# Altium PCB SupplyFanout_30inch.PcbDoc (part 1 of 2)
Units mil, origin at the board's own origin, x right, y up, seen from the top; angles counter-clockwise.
Board outline 6605 x 4500 mil, 4 copper layers (Top Layer, Int1 (GND), Int2 (PWR), Bottom Layer), stack 53.912 mil thick; 152 components, 62 nets, 512 pads, 47 vias.
Unrouted connection lines stored in the file: 85.
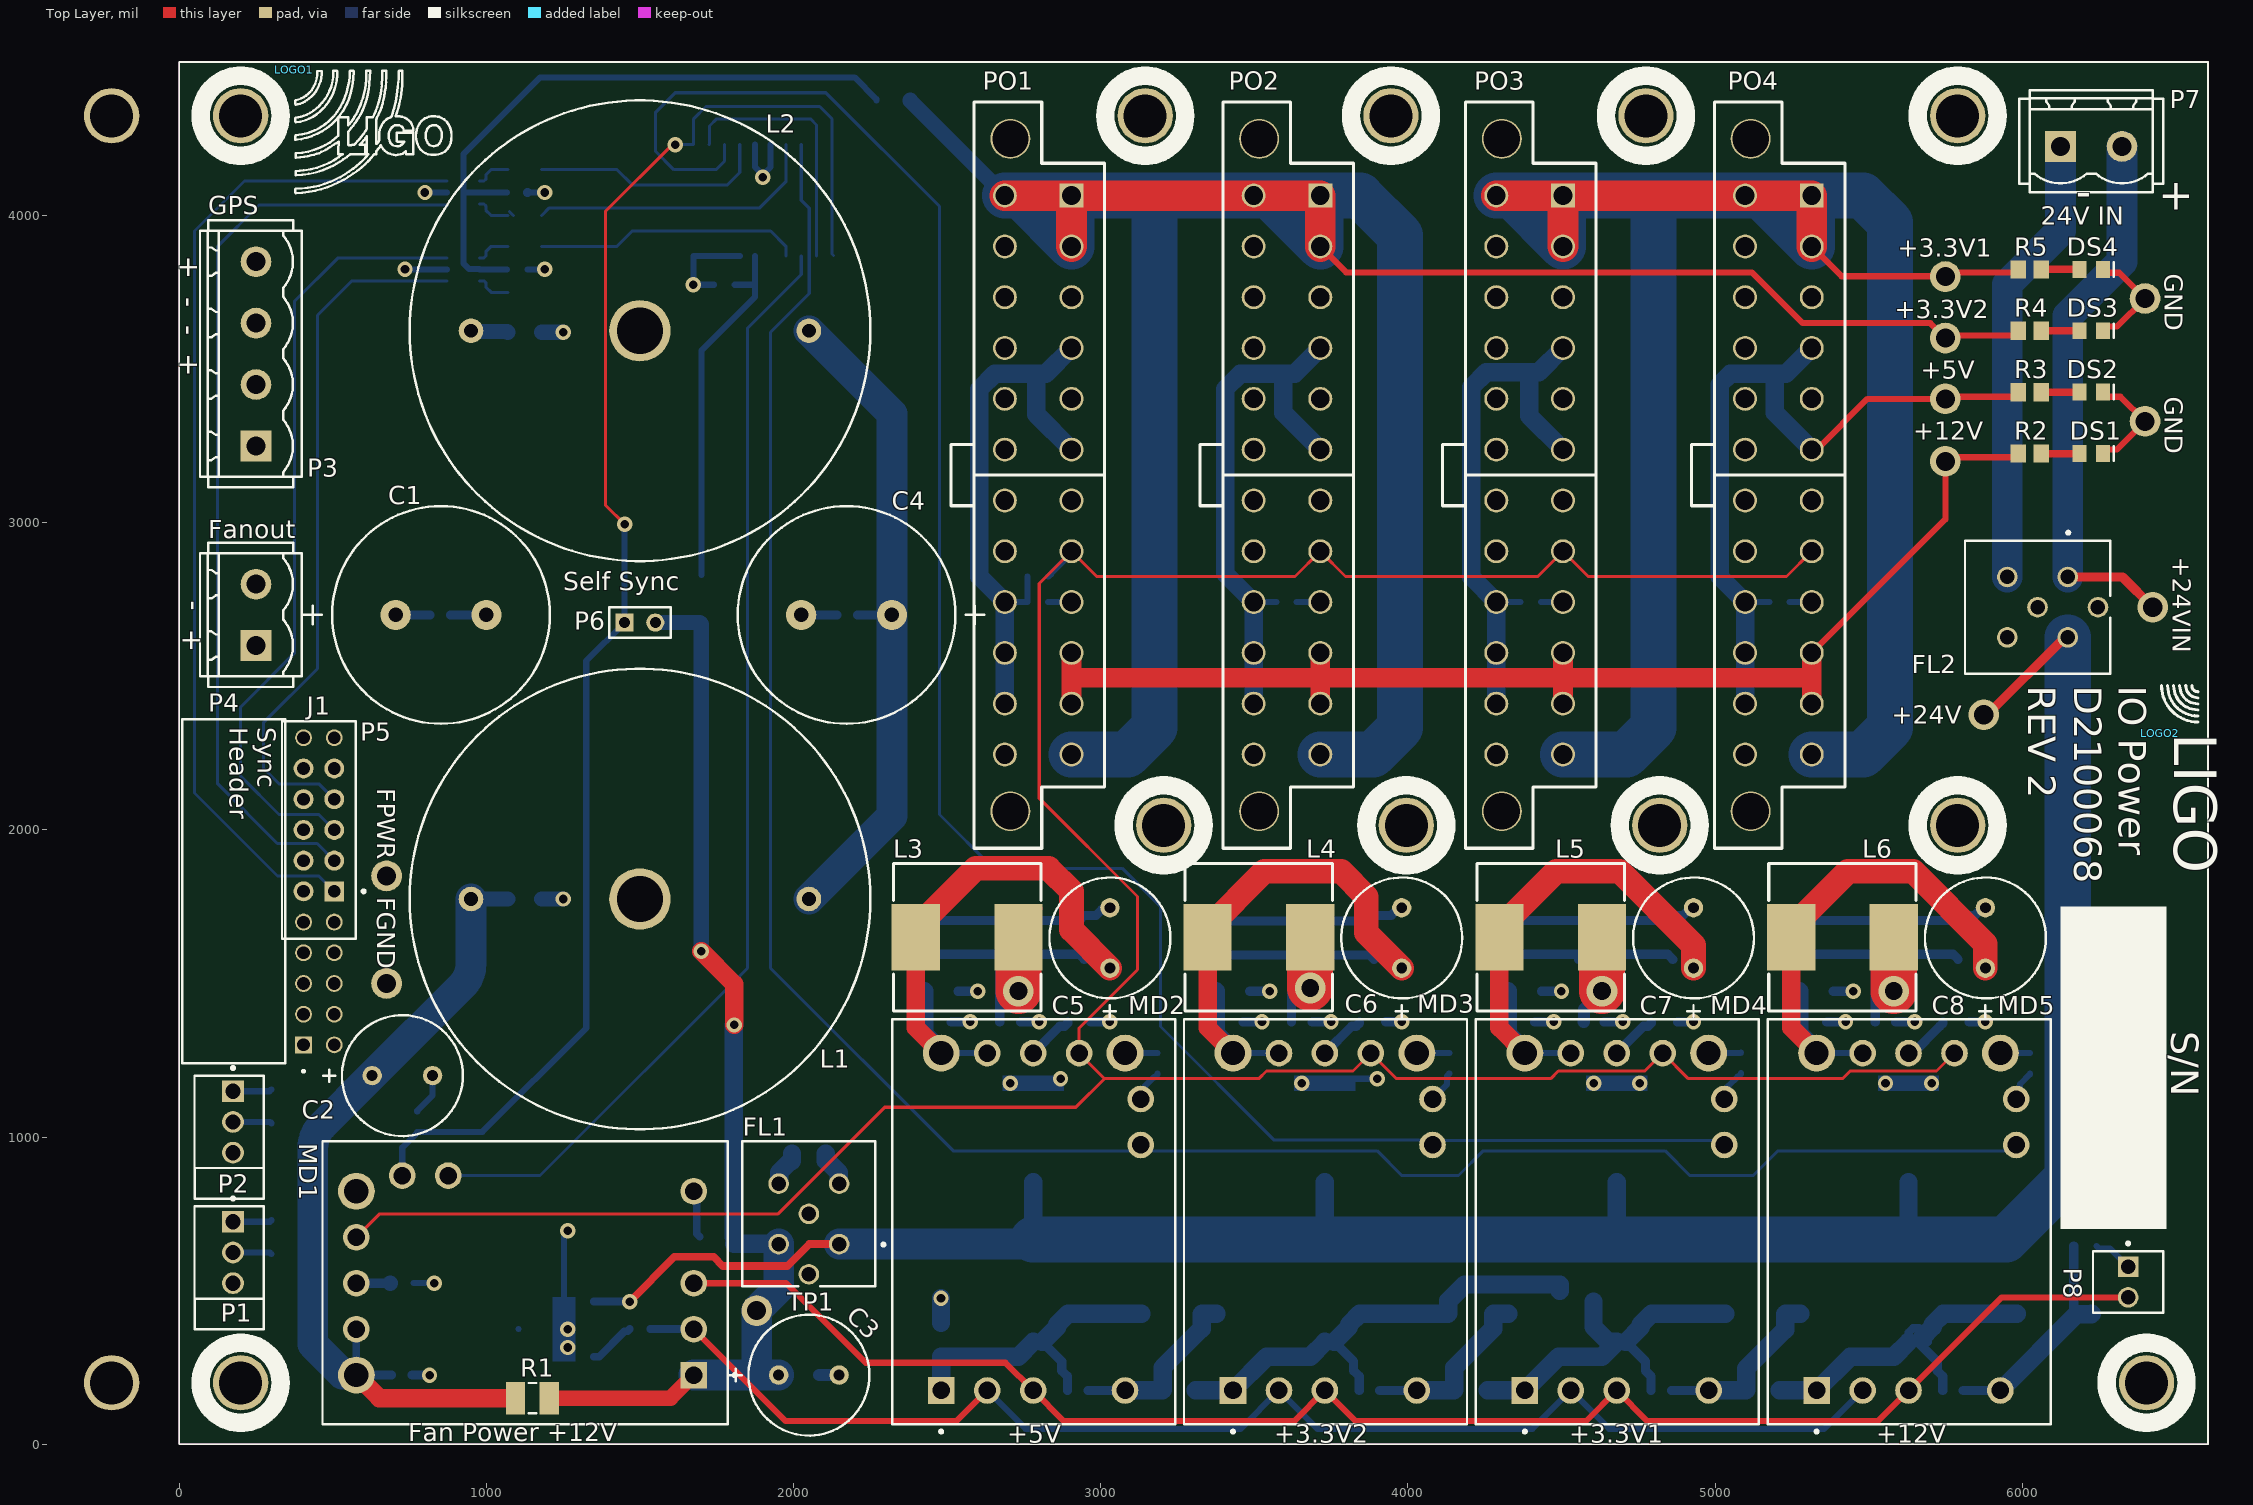
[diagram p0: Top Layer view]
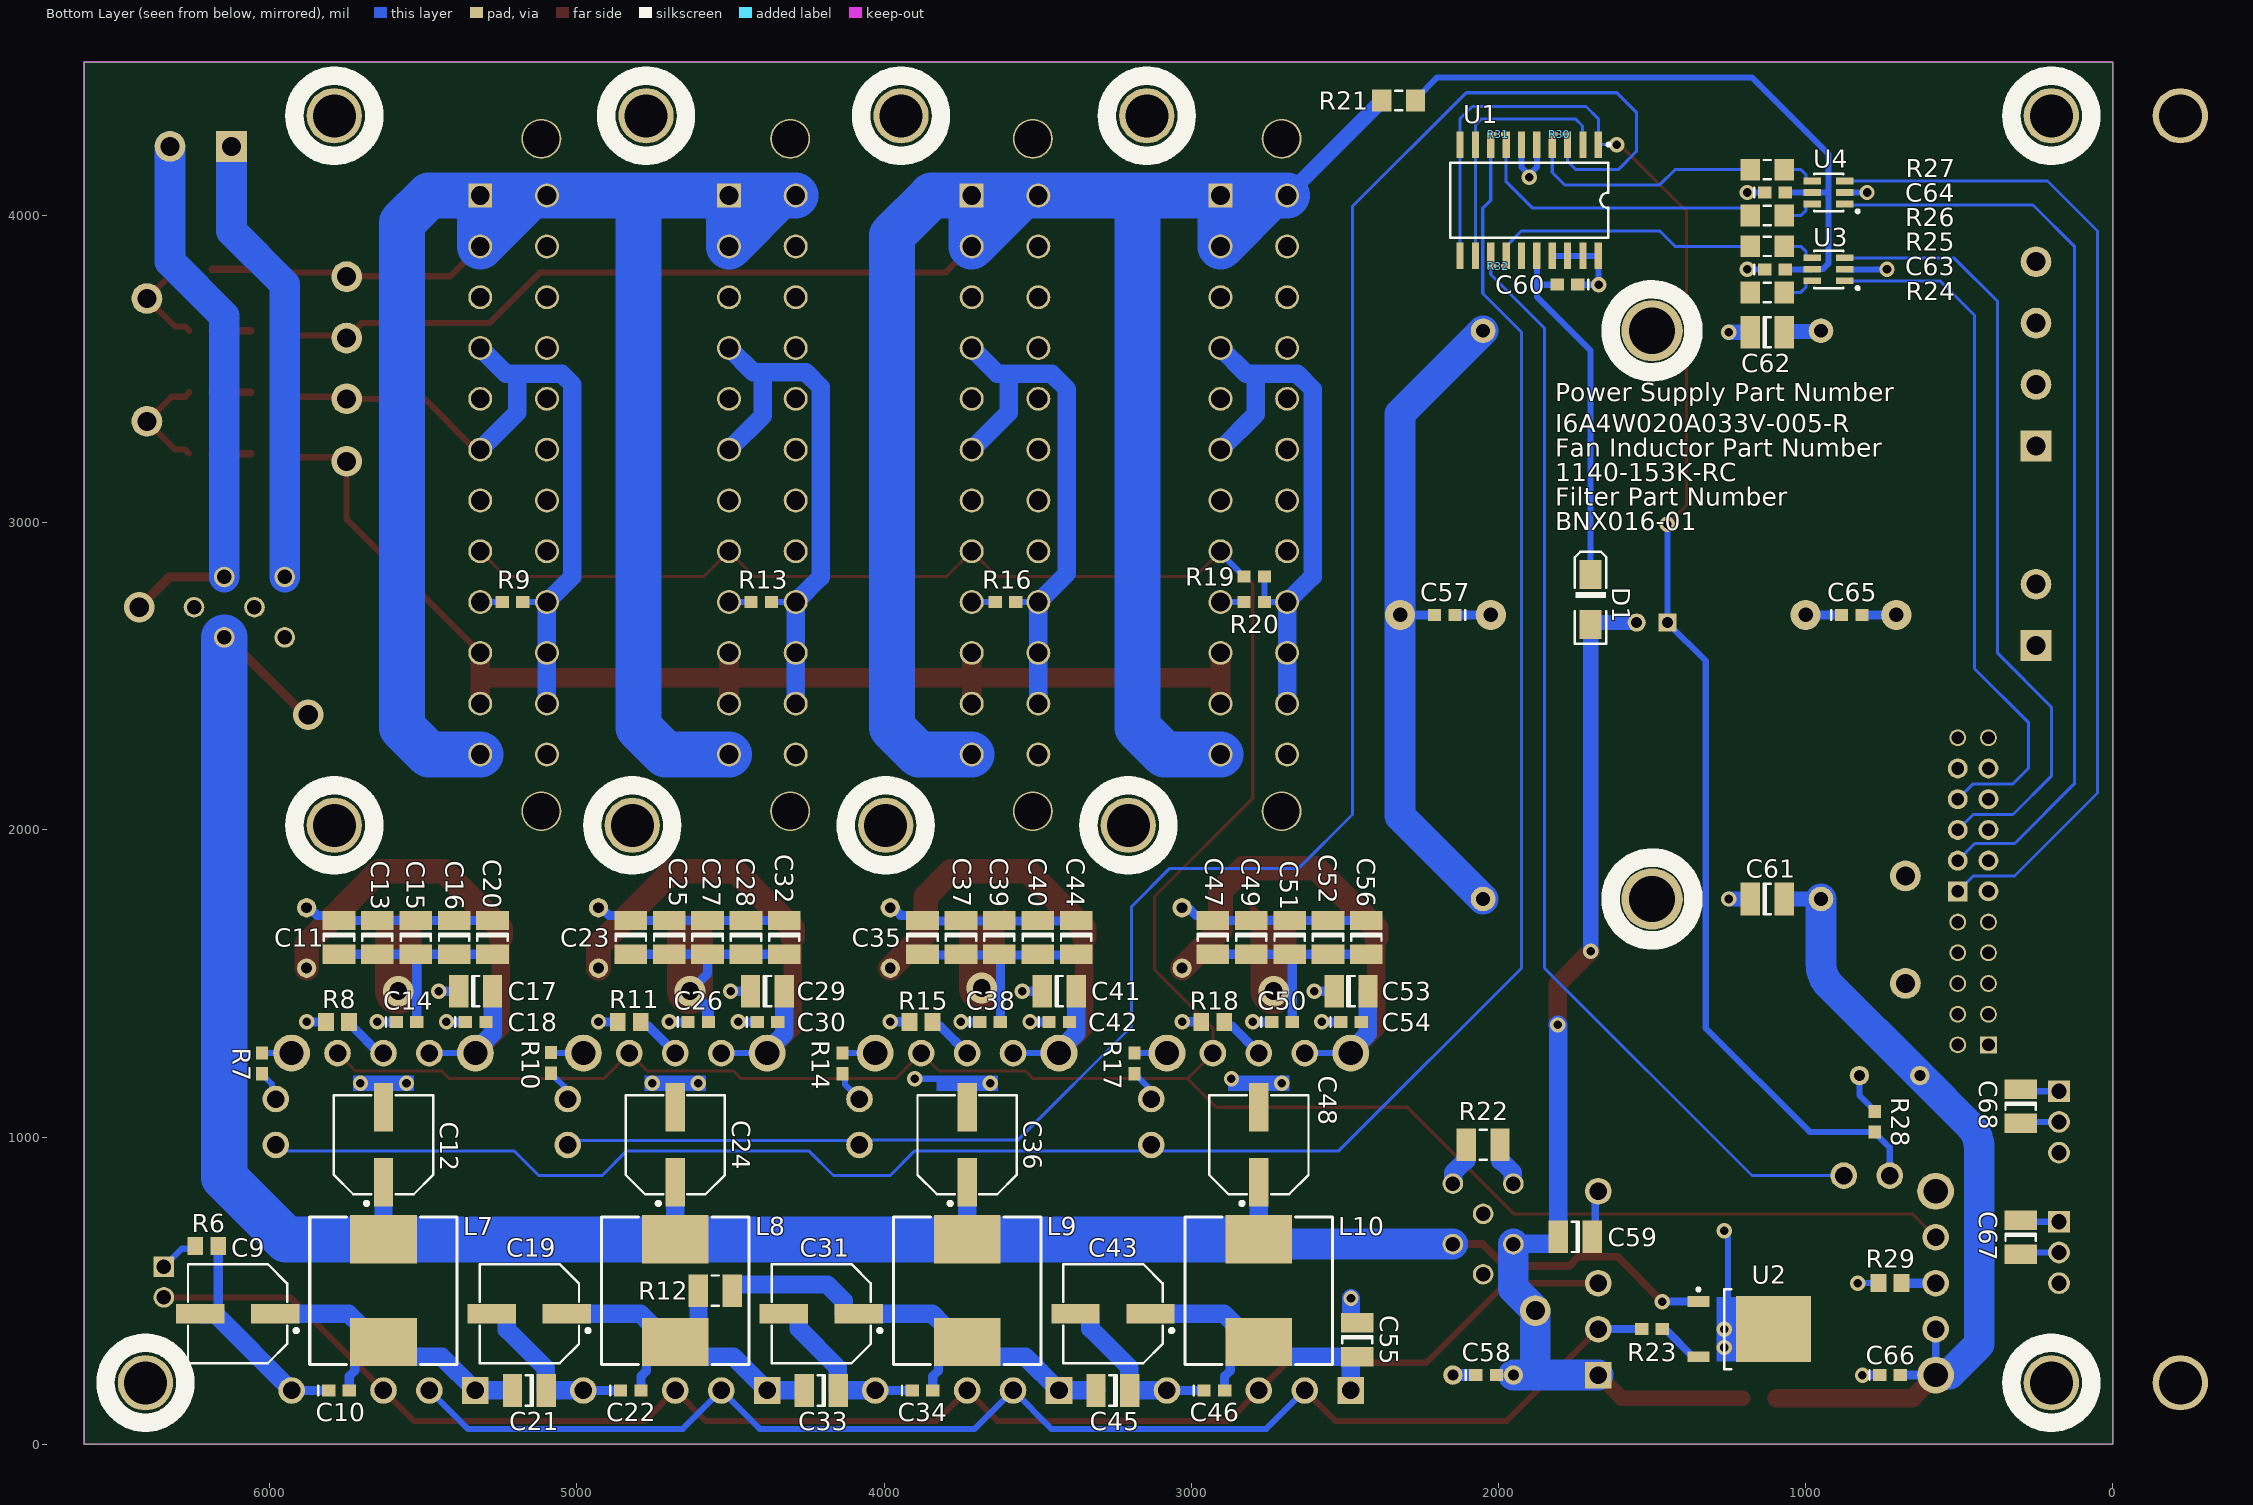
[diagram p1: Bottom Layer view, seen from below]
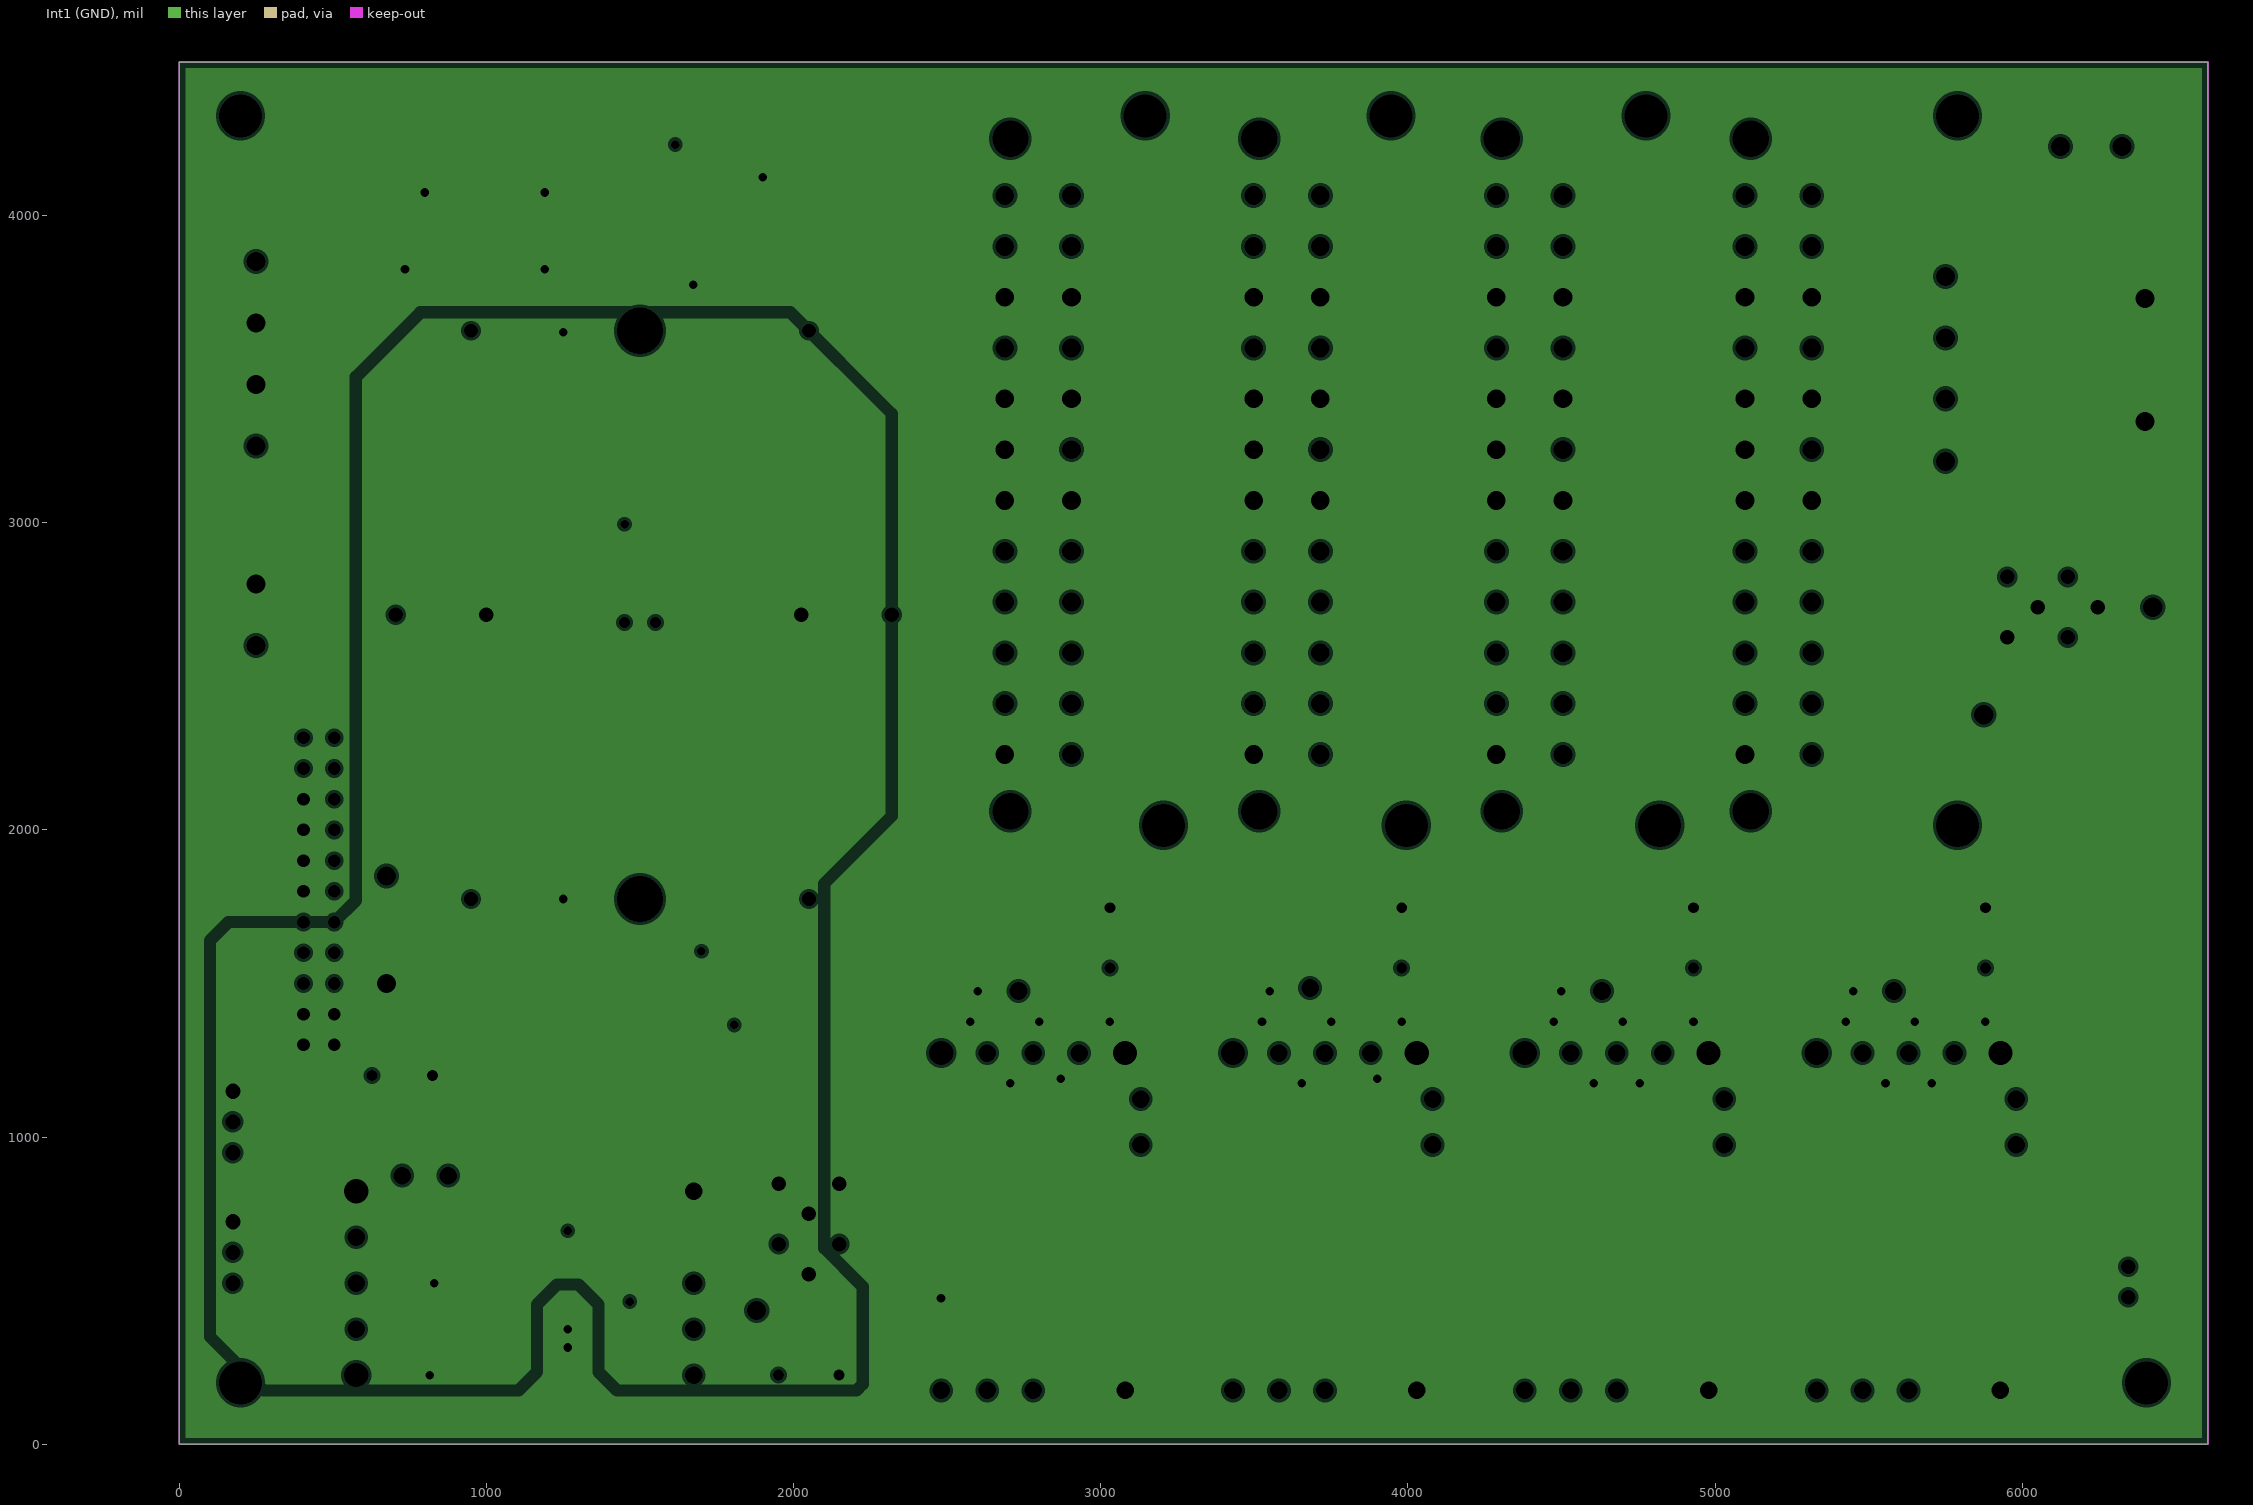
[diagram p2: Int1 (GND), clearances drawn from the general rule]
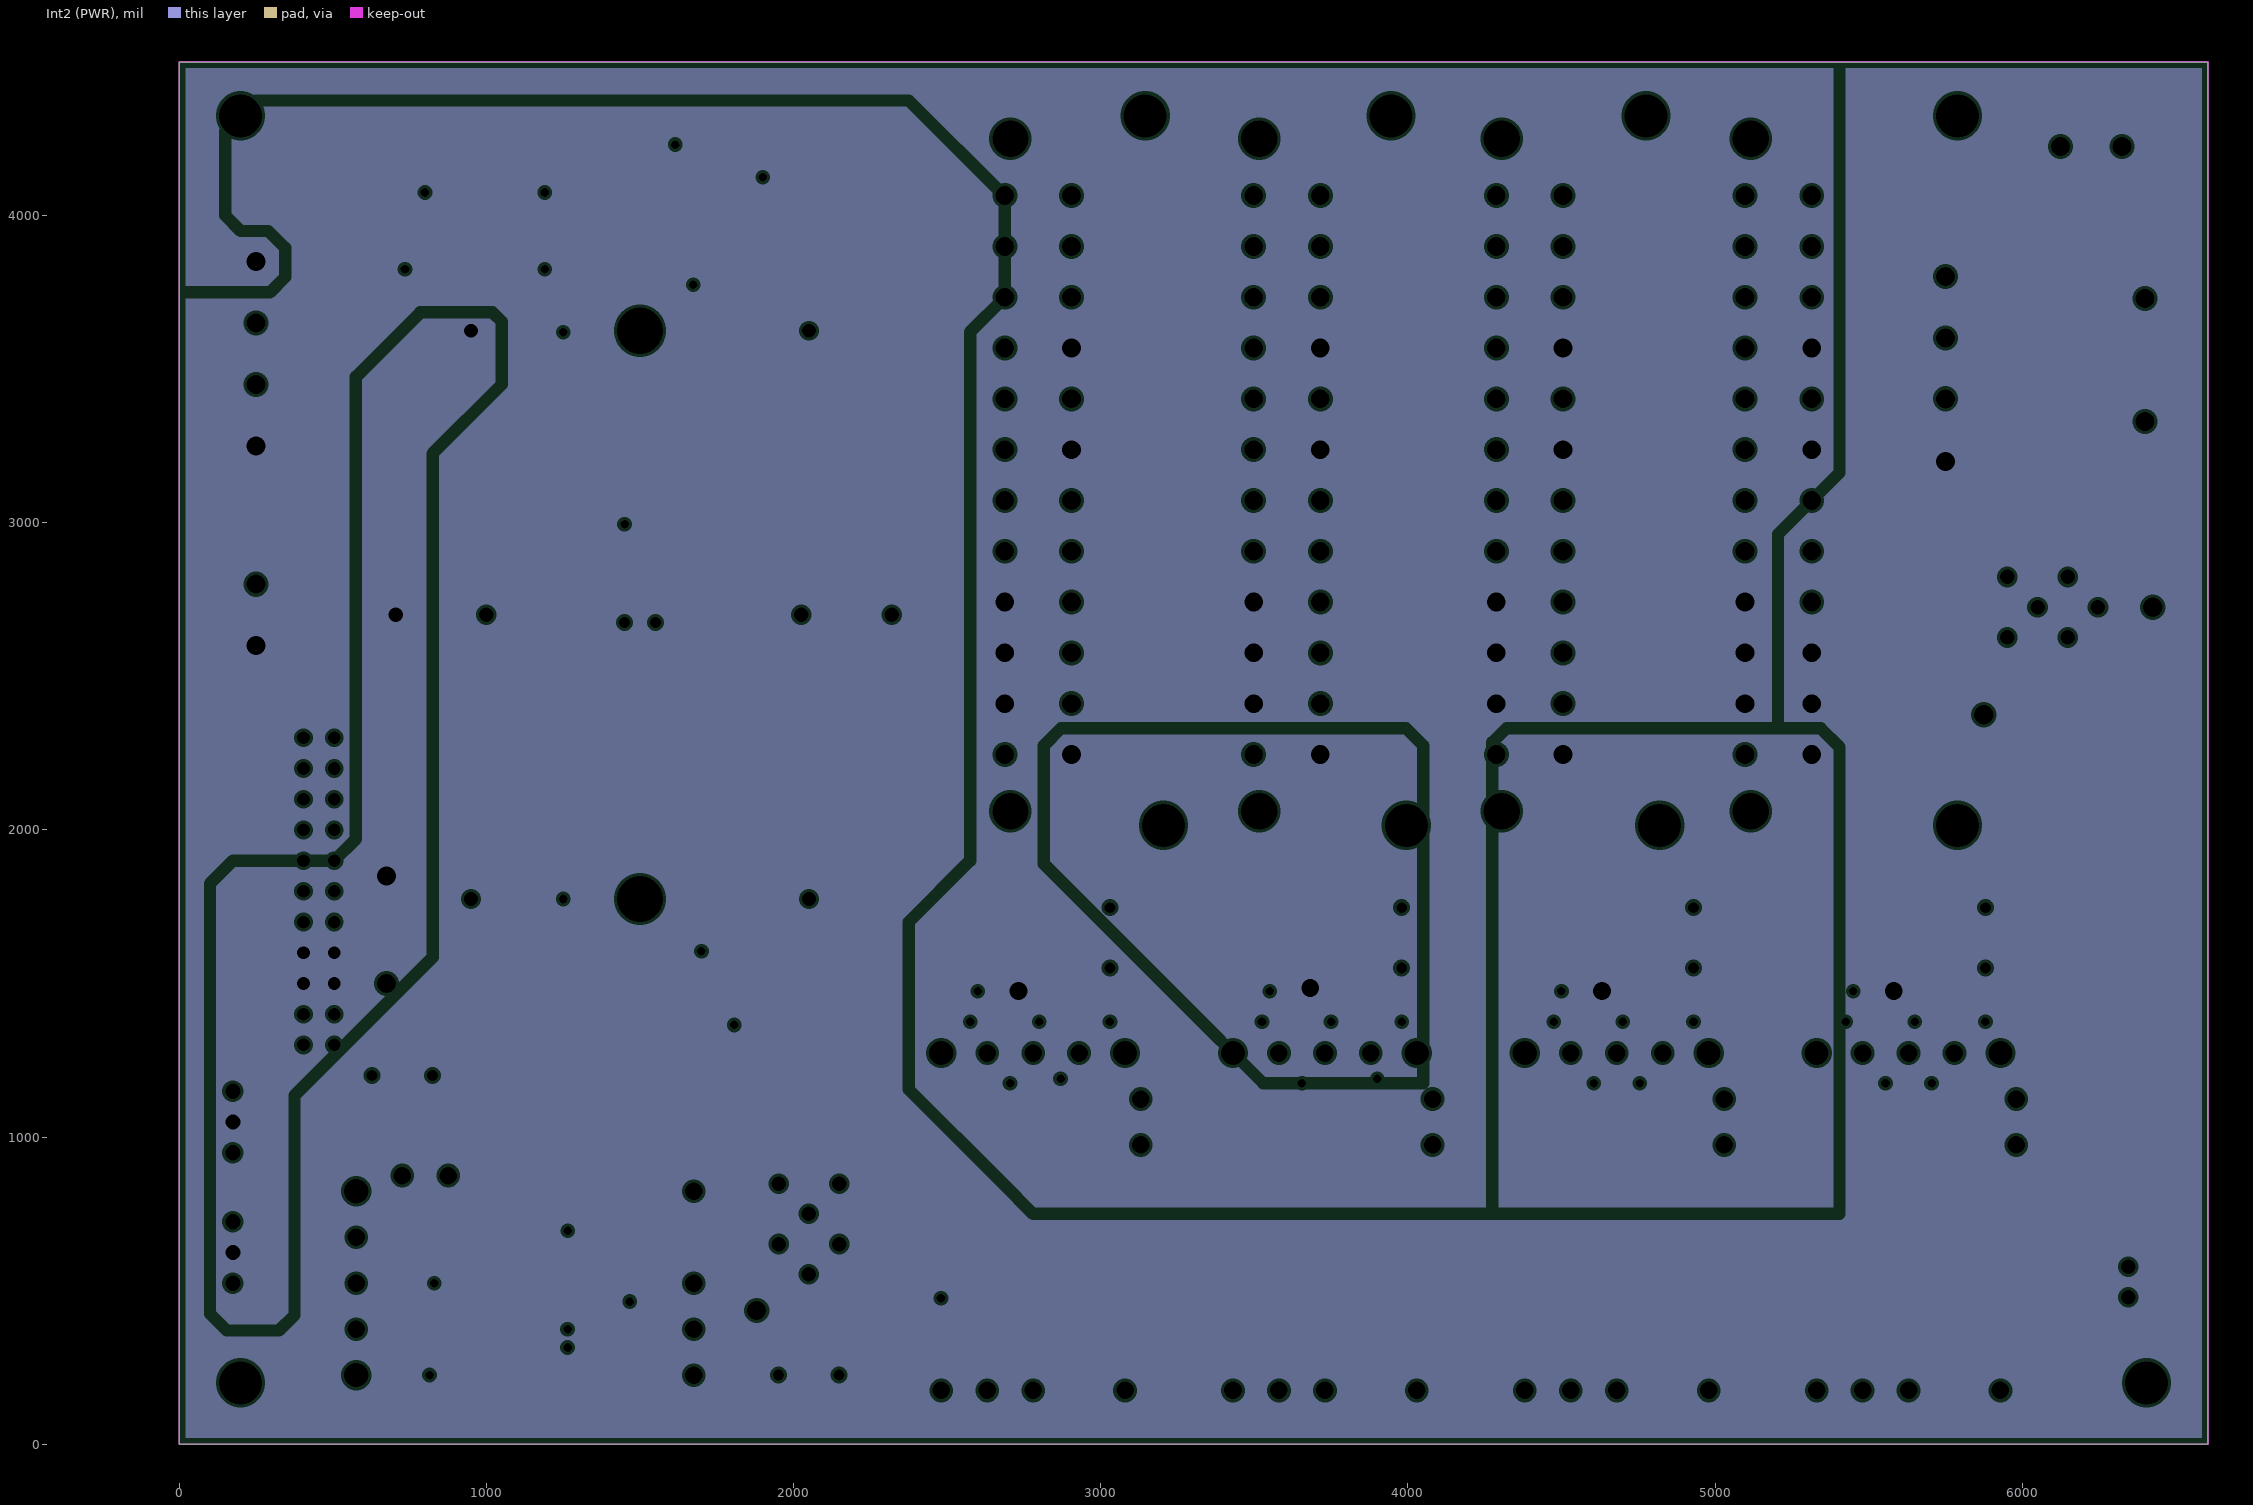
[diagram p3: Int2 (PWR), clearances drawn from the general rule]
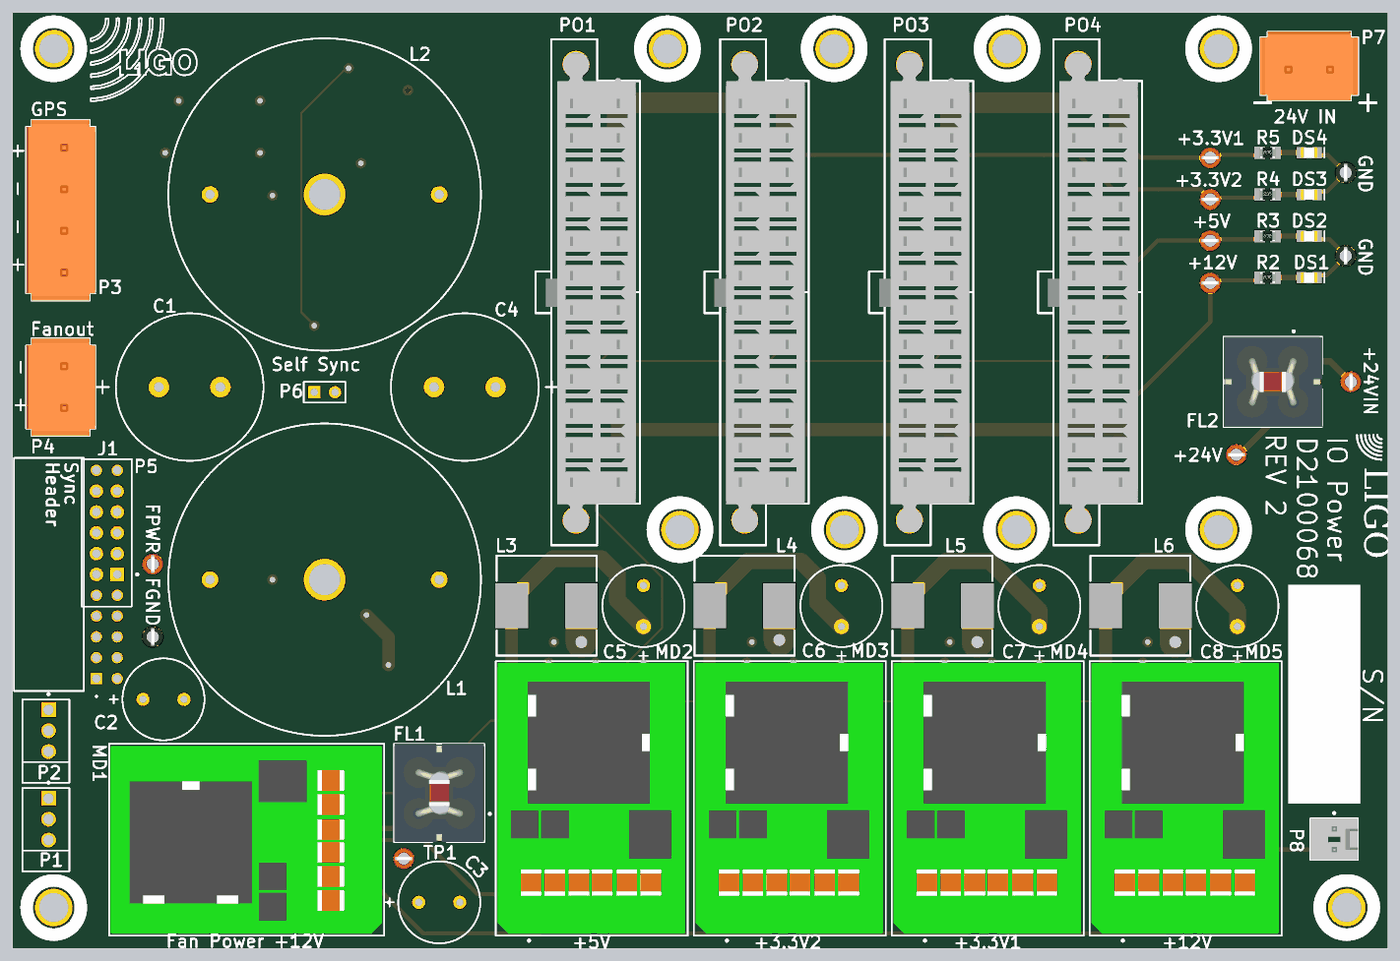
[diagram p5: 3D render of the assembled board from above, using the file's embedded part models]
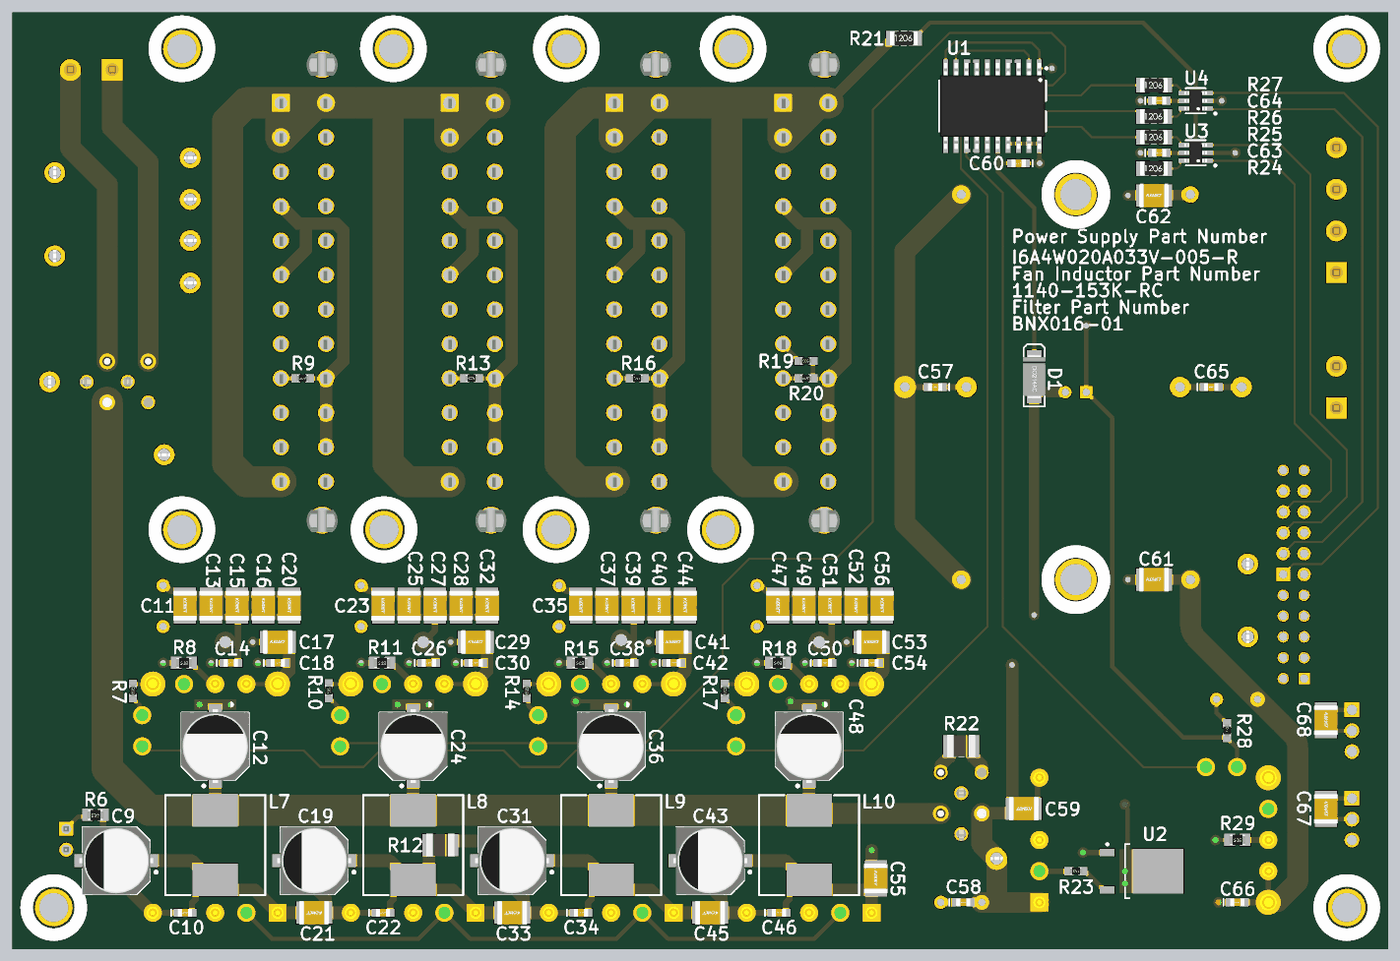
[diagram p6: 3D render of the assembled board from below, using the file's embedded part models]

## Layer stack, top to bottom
Top Solder: solder mask 1, SM-001, Dk 4
Top Layer: signal copper 1.378
Dielectric 1: prepreg 5.1, PP-017, Dk 4.3
Dielectric 2: prepreg 5.1, PP-017, Dk 4.3
Int1 (GND): plane copper 1.378, net (Multiple Nets)
Dielectric 3: core 28, Core-039, Dk 4.8
Int2 (PWR): plane copper 1.378, net (Multiple Nets)
Dielectric 4: prepreg 5.1, PP-017, Dk 4.3
Dielectric 5: prepreg 5.1, PP-017, Dk 4.3
Bottom Layer: signal copper 1.378
Bottom Solder: solder mask 1, SM-001, Dk 4

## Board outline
0,0 0,4500 6605,4500 6605,0

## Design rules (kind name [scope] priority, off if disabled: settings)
Clearance [All] p1: gap=7 ignorepadtopadclearanceinfootprint=FALSE except(0: Arc-Hole Track-Hole SMDPad-Hole THPad-Hole Via-Hole Fill-Hole Poly-Hole Region-Hole Text-Hole; 10: Arc-Fill Arc-Poly Arc-Region Track-Fill Track-Poly Track-Region SMDPad-Fill SMDPad-Poly SMDPad-Region THPad-Fill THPad-Poly THPad-Region Via-Fill Via-Poly Via-Region Fill-Fill Fill-Poly Fill-Region Poly-Poly Poly-Region Region-Region)
ComponentClearance [All] p1: gap=500 collisioncheckmode=3 verticalgap=100000 showdistances=FALSE
DiffPairsRouting [All] p1: maxlimit=10 minlimit=6 mostfreqgap=10 toplayer_minwidth=8 toplayer_maxwidth=15 toplayer_prefwidth=15 bottomlayer_minwidth=8 bottomlayer_maxwidth=15 bottomlayer_prefwidth=15 maxuncoupledlength=500
Height [All] p1: minheight=0 maxheight=2500 prefheight=500
HoleSize [All] p1: absolutevalues=TRUE maxlimit=1000 minlimit=1 maxpercent=80.000 minpercent=20.000
HoleToHoleClearance [All] p1: gap=8 allowstackedmicrovias=TRUE
MinimumSolderMaskSliver [All] p1: minsoldermaskwidth=1
PlaneClearance [All] p1: clearance=10
PlaneConnect [All] p1: planeconnectstyle=Relief reliefexpansion=10 reliefentries=4 reliefconductorwidth=20 reliefairgap=10
PolygonConnect [All] p1: connectstyle=Relief reliefconductorwidth=20 reliefentries=4 polygonreliefangle="90 Angle" airgapwidth=10
RoutingVias [All] p1: holewidth=28 width=50 viastyle="Through Hole" minholewidth=28 minwidth=50 maxholewidth=28 maxwidth=50
SilkToSilkClearance [All] p1: silktosilkclearance=0
SilkToSolderMaskClearance [IsPad] p1: minsilkscreentomaskgap=0.1 clearancetoexposedcopper=TRUE
SolderMaskExpansion [All] p1: expansion=4 istentingtop=FALSE
Width [All] p1: maxlimit=200 minlimit=10 preferedwidth=20
20 further rules are at their usual default settings.

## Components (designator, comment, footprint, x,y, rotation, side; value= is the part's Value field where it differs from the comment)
+3.3V1 "Testpoint" TP1-RED 5750,3801.38 r90 top
+3.3V2 "Testpoint" TP1-RED 5750,3601.38 r90 top
+5V "Testpoint" TP1-RED 5750,3403.4 r90 top
+12V "Testpoint" TP1-RED 5750,3200 r90 top
+24V "Testpoint" TP1-RED 5875,2375 r270 top
+24VIN "Testpoint" TP1-RED 6425,2725 r180 top
C1 "6800uF, 35V" RB18/7.5 704.72,2700 r0 top
C2 "220uF" RB10/5.0 628.15,1200 r0 top
C3 "220uF" RB10/5.0 1951.57,225 r0 top
C4 "6800uF, 35V" RB18/7.5 2320.28,2700 r180 top
C5 "220uF" RB10/5.0 3029.96,1549.76 r90 top
C6 "220uF" RB10/5.0 3980,1549.76 r90 top
C7 "220uF" RB10/5.0 4930,1549.76 r90 top
C8 "220uF" RB10/5.0 5880.28,1549.76 r90 top
C9 "300uF" AC083-033/E 6105,425 r0 bottom
C10 "0.1uF" CC1608-0603 5775,175 r180 bottom
C11 "10uF" CC3225-1210 5775,1650 r270 bottom
C12 "300uF" AC083-033/E 5630,975 r90 bottom
C13 "10uF" CC3225-1210 5650,1650 r270 bottom
C14 "0.1uF" CC1608-0603 5555,1375 r180 bottom
C15 "10uF" CC3225-1210 5525,1650 r270 bottom
C16 "10uF" CC3225-1210 5400,1650 r270 bottom
C17 "10uF" CC3225-1210 5330,1475 r180 bottom
C18 "0.1uF" CC1608-0603 5330,1375 r180 bottom
C19 "300uF" AC083-033/E 5155,425 r0 bottom
C20 "10uF" CC3225-1210 5275,1650 r270 bottom
C21 "10uF" CC3225-1210 5155,175 r0 bottom
C22 "0.1uF" CC1608-0603 4825,175 r180 bottom
C23 "10uF" CC3225-1210 4824.62,1650 r270 bottom
C24 "300uF" AC083-033/E 4680,975 r90 bottom
C25 "10uF" CC3225-1210 4700,1650 r270 bottom
C26 "0.1uF" CC1608-0603 4605,1375 r180 bottom
C27 "10uF" CC3225-1210 4575,1650 r270 bottom
C28 "10uF" CC3225-1210 4450,1650 r270 bottom
C29 "10uF" CC3225-1210 4380,1475 r180 bottom
C30 "0.1uF" CC1608-0603 4380,1375 r180 bottom
C31 "300uF" AC083-033/E 4205,425 r0 bottom
C32 "10uF" CC3225-1210 4325,1650 r270 bottom
C33 "10uF" CC3225-1210 4205,175 r0 bottom
C34 "0.1uF" CC1608-0603 3875,175 r180 bottom
C35 "10uF" CC3225-1210 3875,1650 r270 bottom
C36 "300uF" AC083-033/E 3730,975 r90 bottom
C37 "10uF" CC3225-1210 3750,1650 r270 bottom
C38 "0.1uF" CC1608-0603 3655,1375 r180 bottom
C39 "10uF" CC3225-1210 3625,1650 r270 bottom
C40 "10uF" CC3225-1210 3500,1650 r270 bottom
C41 "10uF" CC3225-1210 3430,1475 r180 bottom
C42 "0.1uF" CC1608-0603 3430,1375 r180 bottom
C43 "300uF" AC083-033/E 3255,425 r0 bottom
C44 "10uF" CC3225-1210 3375,1650 r270 bottom
C45 "10uF" CC3225-1210 3255,175 r0 bottom
C46 "0.1uF" CC1608-0603 2925,175 r180 bottom
C47 "10uF" CC3225-1210 2930,1650 r270 bottom
C48 "300uF" AC083-033/E 2780,975 r90 bottom
C49 "10uF" CC3225-1210 2805,1650 r270 bottom
C50 "0.1uF" CC1608-0603 2705,1375 r180 bottom
C51 "10uF" CC3225-1210 2680,1650 r270 bottom
C52 "10uF" CC3225-1210 2555,1650 r270 bottom
C53 "10uF" CC3225-1210 2480,1475 r180 bottom
C54 "0.1uF" CC1608-0603 2480,1375 r180 bottom
C55 "10uF" CC3225-1210 2460,340 r270 bottom
C56 "10uF" CC3225-1210 2430,1650 r270 bottom
C57 "0.1uF" CC1608-0603 2175,2700 r0 bottom
C58 "0.1uF" CC1608-0603 2040,225 r180 bottom
C59 "10uF" CC3225-1210 1750,675 r0 bottom
C60 "0.1uF" CC1608-0603 1775,3775 r0 bottom (schematic designator C62)
C61 "10uF" CC3225-1210 1125,1775 r180 bottom (schematic designator C65)
C62 "10uF" CC3225-1210 1125,3620 r180 bottom (schematic designator C66)
C63 "0.1uF" CC1608-0603 1100,3825 r180 bottom
C64 "0.1uF" CC1608-0603 1100,4075.29 r180 bottom
C65 "0.1uF" CC1608-0603 850,2700 r180 bottom (schematic designator C67)
C66 "0.1uF" CC1608-0603 725,225 r180 bottom (schematic designator C68)
C67 "10uF" CC3225-1210 300,673.83 r270 bottom (schematic designator C69)
C68 "10uF" CC3225-1210 300,1100 r270 bottom (schematic designator C70)
D1 "shottky diode" DO-SMA 1700,2750 r90 bottom
DS1 "LED" LED-0805 6225,3225 r180 top
DS2 "LED" LED-0805 6225,3425 r180 top
DS3 "LED" LED-0805 6225,3625 r180 top
DS4 "LED" LED-0805 6225,3825 r180 top
FGND "Testpoint" TP1-BLK 675,1500 r180 top
FL1 "BNX016-01" MURA-BNX016-01_V 2050,750 r180 top
FL2 "BNX016-01" MURA-BNX016-01_V 6050,2725 r270 top
FPWR "Testpoint" TP1-RED 675,1850 r180 top
GND "Testpoint" TP1-BLK 6400,3330 r0 top
GND "Testpoint" TP1-BLK 6400,3730 r180 top
J1 "NS" SAMTEC_SSW-111-02-G-D-RA 404.72,1300 r90 top
L1 "Inductor" "Rnd Inductor 45D" 1500,1775 r180 top value=15mH
L2 "Inductor" "Rnd Inductor 45D" 1500,3625 r0 top value=15mH
L3 "750nH" MSS1278 2565,1650 r0 top
L4 "750nH" MSS1278 3515,1650 r0 top
L5 "750nH" MSS1278 4465,1650 r0 top
L6 "750nH" MSS1278 5415,1650 r0 top
L7 "1uH" MSS1278 5630,500 r270 bottom
L8 "1uH" MSS1278 4680,500 r270 bottom
L9 "1uH" MSS1278 3730,500 r270 bottom
L10 "1uH" MSS1278 2780,500 r270 bottom
LOGO1 "LIGO logo" LIGO_LOGO 375,4475 r0 top
LOGO2 "LIGO logo" LIGO-LOGO-SM 6450,2315 r270 top
MD1 "TDK Lambda Sync Power Supply" TDK-Lambda 478.15,973.04 r270 top
MD2 "TDK Lambda Sync Power Supply" TDK-Lambda 3228.83,1371.85 r180 top
MD3 "TDK Lambda Sync Power Supply" TDK-Lambda 4178.83,1371.85 r180 top
MD4 "TDK Lambda Sync Power Supply" TDK-Lambda 5128.83,1371.85 r180 top
MD5 "TDK Lambda Sync Power Supply" TDK-Lambda 6078.83,1371.85 r180 top
P1 "640456-3" TECO-640456-3 175,624.21 r90 top
P2 "640456-3" TECO-640456-3 175,1049.21 r90 top
P3 "TBlock_5.08_4" SL_5_08HC_180B_04 250,3550 r90 top
P4 "TBlock_5.08_2" SL_5_08HC_180B_02 250,2700 r90 top
P5 "09 18 110 9421" 9181109421 454.72,2000 r90 top
P6 "Header 2" HDR1X2 1450,2675 r0 top (schematic designator P8)
P7 "TBlock_5.08_2" SL_5_08HC_180B_02 6225,4225 r0 top (schematic designator P6)
P8 "22-27-2021" MOLX-22-27-2021_V 6344.88,527.95 r270 top (schematic designator P7)
PO1 "Header 12X2A" ATX24Pin_M 2905,4065 r180 top
PO2 "Header 12X2A" ATX24Pin_M 3715,4065 r180 top
PO3 "Header 12X2A" ATX24Pin_M 4505,4065 r180 top
PO4 "Header 12X2A" ATX24Pin_M 5315,4065 r180 top
R1 "NS" CR3225-1210 1150,150 r0 top
R2 "1k" CR2012-0805 6025,3225 r0 top
R3 "500" CR2012-0805 6025,3425 r0 top
R4 "249" CR2012-0805 6025,3625 r0 top
R5 "249" CR2012-0805 6025,3825 r0 top
R6 "10k" CR2012-0805 6205,645 r0 bottom
R7 "NS" CR1608-0603 6025,1240 r90 bottom
R8 "1.82k" CR2012-0805 5780,1375 r0 bottom
R9 "0" CR1608-0603 5210,2741.8 r0 bottom
R10 "NS" CR1608-0603 5085,1241.54 r90 bottom
R11 "30.3k" CR2012-0805 4830,1375 r0 bottom
R12 "NS" CR3225-1210 4550,500 r0 bottom
R13 "0" CR1608-0603 4400,2741.8 r0 bottom
R14 "10k" CR1608-0603 4135,1240 r90 bottom
R15 "30.3k" CR2012-0805 3880,1375 r0 bottom
R16 "0" CR1608-0603 3605,2741.8 r0 bottom
R17 "10k" CR1608-0603 3185,1240 r90 bottom
R18 "8.57k" CR2012-0805 2930,1375 r0 bottom
R19 "10k" CR1608-0603 2795,2825 r0 bottom
R20 "0" CR1608-0603 2795,2741.8 r0 bottom
R21 "0" CR3216-1206 2325,4375 r180 bottom (schematic designator R22)
R22 "NS" CR3225-1210 2050,975 r0 bottom (schematic designator R21)
R23 "10k" CR1608-0603 1500,375 r180 bottom (schematic designator R24)
R24 "0" CR3216-1206 1125,3750 r180 bottom (schematic designator R26)
R25 "0" CR3216-1206 1125,3900 r180 bottom (schematic designator R27)
R26 "0" CR3216-1206 1125,4000 r180 bottom (schematic designator R28)
R27 "0" CR3216-1206 1125,4149.53 r180 bottom (schematic designator R29)
R28 "10k" CR1608-0603 775,1050 r90 bottom (schematic designator R23)
R29 "1.82k" CR2012-0805 725,525 r0 bottom (schematic designator R30)
R30 "NS" CR0603-0201 1800,4265 r180 bottom
R31 "NS" CR0603-0201 2000,4265 r0 bottom
R32 "NS" CR0603-0201 2000,3835 r0 bottom
TP1 "Testpoint" TP1-RED 1880,435 r270 top
U1 "MAX333A" SO-G20 1900,4050 r0 bottom (schematic designator U99)
U2 "LD29150DT33R" TO-252_L 1183.74,374.61 r180 bottom (schematic designator U4)
U3 "SN74LVC2G34" SO-G6/E2.4 925,3825 r90 bottom (schematic designator U5)
U4 "SN74LVC2G34" SO-G6/E2.4 925,4075 r90 bottom (schematic designator U6)

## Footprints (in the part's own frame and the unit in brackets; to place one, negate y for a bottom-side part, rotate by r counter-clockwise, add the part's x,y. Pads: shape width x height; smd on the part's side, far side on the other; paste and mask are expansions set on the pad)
9181109421 [mm] "Connector; IDC, PCB Transition - 2 Rows, Thru-Hole; 10 Position; Vertical; Pitch 2.54 mm; Body 18.00 x 6.1 x 7.45 mm (LxWxH), Kinked Contacts"
  rect 1.65x1.65 hole 1: 1(-5.08,-1.27)
  round 1.65 hole 1: 2(-5.08,1.27) 3(-2.54,-1.27) 4(-2.54,1.27) 5(0,-1.27) 6(0,1.27) 7(2.54,-1.27) 8(2.54,1.27) 9(5.08,-1.27) 10(5.08,1.27)
  silkscreen extent -9,-3.83 9,3.05
AC083-033/E [mm] "SMT Electrolyte Capacitor; E Size, Body 8.3 x 8.3 mm (LxW typ)"
  rect 4x1.6 smd: 1(-3.1,0) 2(3.1,0)
  silkscreen extent -5,-4.1 4.1,4.1, body extent -4.5,-4.15 4.5,4.15, height 6.2
ATX24Pin_M [mil] "ATX 24 pin header male, power, 4.2mm"
  rect 78x78 hole 61: 1(0,0)
  round 78 hole 61: 2(0,165.4) 3(0,330.8) 4(0,496.2) 5(0,661.6) 6(0,827) 7(0,992.4) 8(0,1157.8) 9(0,1323.2) 10(0,1488.6) 11(0,1654) 12(0,1819.4) 13(217,0) 14(217,165.4) 15(217,330.8) 16(217,496.2) 17(217,661.6) 18(217,827) 19(217,992.4) 20(217,1157.8) 21(217,1323.2) 22(217,1488.6) 23(217,1654) 24(217,1819.4)
  round 130 hole 118: 25(199,-184.8) 26(199,2004.2)
  silkscreen extent -108,-305 392,2125, body extent -89,-237 344,2061, height 504
CC1608-0603 [mm] "Chip Capacitor; Body 1.6 x 0.8 mm (LxW typ)"
  rect 1.1x1 smd: 1(-0.85,0) 2(0.85,0)
  silkscreen extent -1.7,-0.4 -1.7,0.4, body extent -0.88,-0.48 0.87,0.47, height 0.87
CC3225-1210 [mm] "Chip Capacitor; Body 3.2 x 2.5 mm (LxW typ)"
  rect 1.6x2.7 smd: 1(-1.4,0) 2(1.4,0)
  silkscreen extent -0.3,-1.25 0.3,1.25, body extent -1.85,-1.45 1.85,1.45, height 1.4
CR0603-0201 [mm] "Chip Resistor; Body 0.6 x 0.3 mm (LxW typ)"
  rect 0.7x0.4 smd: 1(-0.525,0) 2(0.525,0)
CR1608-0603 [mm] "Chip Resistor; Body 1.6 x 0.8 mm (LxW typ)"
  rect 1.1x1 smd: 1(-0.85,0) 2(0.85,0)
  body extent -0.76,-0.43 0.79,0.42, height 0.46
CR2012-0805 [mm] "Chip Resistor; Body 2.0 x 1.3 mm (LxW typ)"
  rect 1.3x1.5 smd: 1(-0.95,0) 2(0.95,0)
  body extent -1,-0.62 1,0.63, height 0.46
CR3216-1206 [mm] "Chip Resistor; Body 3.2 x 1.6 mm (LxW typ)"
  rect 1.6x1.8 smd: 1(-1.4,0) 2(1.4,0)
  silkscreen extent -0.3,-0.8 0.3,0.8, body extent -1.67,-0.86 1.68,0.87, height 0.85
CR3225-1210 [mm] "Chip Resistor; Body 3.2 x 2.5 mm (LxW typ)"
  rect 1.6x2.7 smd: 1(-1.4,0) 2(1.4,0)
  silkscreen extent -0.3,-1.25 0.3,1.25, body extent -1.73,-1.37 1.73,1.37, height 0.71
DO-SMA [mm] "DO-214-AC/SMA; 2 C-Bend Leads; Body 5 x 2.7 mm, inc. leads (LxW)"
  rect 2.4x1.8 smd: 1(-2.05,0) 2(2.05,0)
  silkscreen extent -3.65,-1.3 3.95,1.3, body extent -2.74,-1.4 2.74,1.4, height 2.41
HDR1X2 [mm] "Connector; Header; 2 Position"
  rect 1.5x1.5 hole 0.9: 1(0,0)
  round 1.5 hole 0.9: 2(2.54,0)
  silkscreen extent -1.27,-1.27 3.81,1.27
LED-0805 [mm] "SMD LED, 805, Body 2.0 x 1.3 mm (LxW typ)"
  rect 1.15x1.4 smd: 1(-0.975,0) 2(0.975,0)
  silkscreen extent -1.85,-0.6 -1.85,0.6, body extent -1,-0.62 1,0.63, height 0.75
LIGO-LOGO-SM [mil] "Smaller Ligo Logo"
  silkscreen extent -154,4 -36,122
LIGO_LOGO [mil] "LIGO logo"
  silkscreen extent 3,-402 511,-3
MOLX-22-27-2021_V [mm] "Header, 2-Leads, Body 5.8x5.08mm"
  rect 1.7x1.7 hole 1.19: 1(-1.27,0)
  round 1.7 hole 1.19: 2(1.27,0)
  silkscreen extent -3.31,-2.9 2.54,2.9, body extent -2.54,-2.9 2.54,2.9, height 11.72
MSS1278 [mil] "Power Inductor, MSS1278 series, Coilcraft"
  rect 157x217 smd: 1(-167,0) 2(167,0)
  silkscreen extent -240,-240 240,240
MURA-BNX016-01_V [mm] "THD, 6-Leads, Body 12x11mm"
  round 1.7 hole 1.2: 1(-2.5,2.5) 2(2.5,2.5) 3(-2.5,-2.5) 4(2.5,-2.5) 5(0,0) 6(0,5)
  silkscreen extent -6.29,-6 5.5,6, body extent -5.5,-6 5.5,6, height 8
RB10/5.0 [mm] "Electrolyte, radial, 10mm diameter"
  round 1.6 hole 0.9: 1(0,0) 2(5,0)
  silkscreen extent -4.06,-5 7.5,5
RB18/7.5 [mm] "Electrolyte, radial, 18mm diameter"
  round 2.5 hole 1.2: 1(0,0) 2(7.5,0)
  silkscreen extent -7.62,-9 12.75,9
"Rnd Inductor 45D" [mil] "Footprint for Bourns 1140 Inductors with smaller pin Dia."
  round 80 hole 45: 1(-550,0) 2(550,0)
  round 200 hole 150: 11(0,0)
  silkscreen extent -750,-750 750,750, body extent -750,-750 750,750, height 1030
SAMTEC_SSW-111-02-G-D-RA [mm]
  rect 1.39x1.39 hole 1.04: 01(0,0)
  round 1.39 hole 1.04: 02(0,-2.54) 03(2.54,0) 04(2.54,-2.54) 05(5.08,0) 06(5.08,-2.54) 07(7.62,0) 08(7.62,-2.54) 09(10.16,0) 10(10.16,-2.54) 11(12.7,0) 12(12.7,-2.54) 13(15.24,0) 14(15.24,-2.54) 15(17.78,0) 16(17.78,-2.54) 17(20.32,0) 18(20.32,-2.54) 19(22.86,0) 20(22.86,-2.54) 21(25.4,0) 22(25.4,-2.54)
  silkscreen extent -2.27,-0.1 26.93,10.03
SL_5_08HC_180B_02 [mil] "OMNIMATE Signal - Serie BL/SL 5.08  SL 5.08HC/02/180B 3.2"
  rect 100x100 hole 62: 1(-100,0)
  round 100 hole 62: 2(100,0)
  silkscreen extent -235,-149 235,182, body extent -235,-149 235,182, height 473
SL_5_08HC_180B_04 [mil] "OMNIMATE Signal - Serie BL/SL 5.08  SL 5.08HC/04/180B 3.2"
  rect 100x100 hole 62: 1(-300,0)
  round 100 hole 62: 2(-100,0) 3(100,0) 4(300,0)
  silkscreen extent -435,-149 435,182, body extent -435,-149 435,182, height 473
SO-G6/E2.4 [mm] "Small Outline; 6 Leads; Body 3.6 x 3.6 mm, inc. leads (LxW max)"
  rect 0.55x1.45 smd: 1(-0.95,-1.35) 2(0,-1.35) 3(0.95,-1.35) 4(0.95,1.35) 5(0,1.35) 6(-0.95,1.35)
  silkscreen extent -1.67,-2.52 1.55,1.2, body extent -1.45,-1.4 1.45,1.4, height 1.45
SO-G20 [mm] "Small Outline; 20 Leads; Body Width 7.5 mm; Pitch 1.27 mm"
  rect 0.6x2.2 smd: 1(-5.715,-4.6) 2(-4.445,-4.6) 3(-3.175,-4.6) 4(-1.905,-4.6) 5(-0.635,-4.6) 6(0.635,-4.6) 7(1.905,-4.6) 8(3.175,-4.6) 9(4.445,-4.6) 10(5.715,-4.6) 11(5.715,4.6) 12(4.445,4.6) 13(3.175,4.6) 14(1.905,4.6) 15(0.635,4.6) 16(-0.635,4.6) 17(-1.905,4.6) 18(-3.175,4.6) 19(-4.445,4.6) 20(-5.715,4.6)
  silkscreen extent -6.69,-4.72 6.53,3.1, body extent -6.42,-5.24 6.43,5.24, height 2.65
TDK-Lambda [mm] "Power Supply"
  rect 2.2x2.2 hole 1.45 paste-1000 mask+0: 1(19,30.4)
  round 2.2 hole 1.45 paste-1000 mask+0: 2(11.4,30.4) 3(3.8,30.4) 5(7.6,2.5) 6(11.4,2.5) 7(15.2,2.5) 32(2.5,10.1) 33(2.5,6.3) 34(15.2,30.4)
  round 3.05 hole 2 paste-1000 mask+0: 4(3.8,2.5) 8(19,2.5)
  silkscreen extent -0.35,-0.3 23.05,33.92, body extent -0.45,-0.4 23.15,33.3, height 0.25
TECO-640456-3 [mm] "Through Hole, 3-Leads, Body 7.62x5.72mm, Pitch 2.54mm"
  rect 1.8x1.8 hole 1.27 paste+0: 1(2.54,0)
  round 1.8 hole 1.27 paste+0: 2(0,0) 3(-2.54,0)
  silkscreen extent -3.81,-2.54 4.59,3.18, body extent -3.81,-2.54 3.81,3.18, height 10.03
TO-252_L [mm] "D-PAK, 4-Leads, Body 6.1x6.5mm, Pitch 2.28mm, Lead Span 9.7mm, IPC High Density"
  rect 1.8x0.9 smd: 1(-4.2,2.28) 3(-4.2,-2.28)
  rect 6.2x5.45 smd: 4(2,0)
  silkscreen extent -4.33,-3.3 -1.5,3.4, body extent -2.05,-3.3 4.15,3.3, height 2.4
TP1-BLK [mm] "Testpoint pin, black"
  round 2.54 hole 1.58: 1(0,0)
  body extent -1.27,-1.27 1.27,1.27, height 4.89
TP1-RED [mm] "Testpoint pin, red"
  round 2.54 hole 1.58: 1(0,0)
  body extent -1.27,-1.27 1.27,1.27, height 4.89

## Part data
+3.3V1 +3.3V2 +5V +12V +24V +24VIN FPWR TP1: library part TP_POSITIVE, "Testpoint, red", Part Number=36-5005-ND
C1: library part CapRadial, "Electrolyte capacitor, leaded, radial  / 1189-3996-ND", Manufacturer=Nichicon, Supplier Part Number 1=1189-3996-ND, Tolerance=20%
C2 C3 C5 C6 C7 C8: library part CapRadial, "Electrolyte capacitor, leaded, radial", Manufacturer=Nichicon, Supplier Part Number 1=399-18266-1-ND, Tolerance=20%
C4: library part CapRadial, "Electrolyte capacitor, leaded, radial   / 1189-3996-ND", Manufacturer=Nichicon, Supplier Part Number 1=1189-3996-ND, Tolerance=20%
C9 C12 C19 C24 C31 C36 C43 C48: library part ChipElectrolyte, "Electrolyte capacitor, surface mount", Supplier Part Number 1=PCE5025CT-ND, Tolerance=20%, Voltage Rating=50V
C10 C14 C18 C22 C26 C30 C34 C38 C42 C46 C50 C54 C57 C58 C60 C63 C64 C65 C66: library part ChipCap, "Capacitor, surface mount", Supplier Part Number 1=1276-6807-1-ND, Tolerance=10%
C11 C13 C15 C16 C17 C20 C21 C23 C25 C27 C28 C29 C32 C33 C35 C37 C39 C40 C41 C44 C45 C47 C49 C51 C52 C53 C55 C56 C59 C61 C62 C67 C68: library part ChipCap, "Capacitor, surface mount", Supplier Part Number 1=7661214P, Tolerance=10%
D1: library part DIODE_SHOTTKY, "Single shottky diode"
DS1 DS2 DS3 DS4: "Panel mount LED", Supplier Part Number 1=732-4986-1-ND
FGND GND GND: library part TP_GND, "Testpoint, black", Part Number=36-5006-ND
FL1 FL2: library part CMP-2000-05960-1, "Block Type EMIFIL(R) Reference Specification, 15 A, 25 V, -40 to 125 degC, 6-Pin THD, RoHS, Bulk", Part Number=490-5055-ND
J1: library part SSW-111-02-G-D-RA, Package=None
L1 L2: Digikey Part Number=M8387-ND
L3 L4 L5 L6: library part MSS1278, "Power inductor, MSS1278 series", Supplier Part Number 1=732-4118-1-ND
L7 L8 L9 L10: library part MSS1278, "Power inductor, MSS1278 series", Supplier Part Number 1=308-1334-1-ND
LOGO1 LOGO2: library part LIGO_logo
MD1 MD2 MD3 MD4 MD5: library part TDK-Lambda, "i6A4W020A033V-005-R", Supplier Part Number 1=285-I6A4W020A033V-005-R-ND
P1 P2: library part CMP-2000-05418-1, "Male Header, Pitch 2.54 mm, 1 x 3 Position, Height 10.03 mm, Tail Length 3.56 mm, -55 to 105 degC", Color=White, Current, Rating="5 /  / A", Flammability Rating=UL94V-0, Manufacturer="TE Connectivity", Temperature, Operating="-55to+105 /  / degC", Voltage, Rating="250 /  / V"
P3: "Terminal block, 5.08mm, 4-Pin", Part Number=281-1299-ND, Supplier Part Number 1=732-2060-ND
P4 P7: "Terminal block, 5.08mm, 2-Pin", Part Number=281-1297-ND, Supplier Part Number 1=ED2843-ND
P5: "Flat Cable Connector (IDC), PCB Transition Connector, 2 Rows, Kinked Solder Pin, 10 Contacts", PackageDocument=16-Sep-2003, Supplier Part Number 1=ED1543-ND
P6: "Header, 2-Pin"
P8: library part CMP-2000-05537-1, "Male Header, Pitch 2.54 mm, 1 x 2 Position, Height 11.7 mm, Tail Length 3.56 mm, 0 to 75 degC, RoHS, Bulk", Current - Max=4A, Manufacturer=Molex, Operating Temperature=0°Cto+75°C, Package Description="2-Leads Header, Body 5.08 x 5.8 mm, Pitch 2.54 mm", Package Version="Rev. BC, 02/2012", PartNumber=0022272021, Voltage - Max=250V
PO1 PO2 PO3 PO4: library part ATX24PIN_MALE, "Header, 12-Pin, Dual row, ATX power, board", Manufacturers Part Number=39-29-9246, Part Number=WM9738-ND
R1 R7 R10 R12 R22 R28: library part ChipRes1, "Resistor, surface mount", Tolerance=1%
R2: library part ChipRes1, "Resistor, surface mount", Supplier Part Number 1=311-1.00KCRCT-ND, Tolerance=1%
R3: library part ChipRes1, "Resistor, surface mount", Supplier Part Number 1=P499DACT-ND, Tolerance=1%
R4: library part ChipRes1, "Resistor, surface mount", Supplier Part Number 1=541-249CCT-ND, Tolerance=1%
R5: library part ChipRes1, "Resistor, surface mount", Supplier Part Number 1=P249DACT-ND, Tolerance=1%
R6 R14 R17 R19 R23 R30 R31 R32: library part ChipRes1, "Resistor, surface mount", Supplier Part Number 1=P10KDACT-ND, Tolerance=1%
R8 R29: library part ChipRes1, "Resistor, surface mount", Supplier Part Number 1=P1.82KDACT-ND, Tolerance=1%
R9 R13 R16 R20: library part ChipRes1, "Resistor, surface mount", Supplier Part Number 1=2019-RK73Z1JTTDCT-ND, Tolerance=1%
R11 R15: library part ChipRes1, "Resistor, surface mount", Supplier Part Number 1=P30.1KDACT-ND, Tolerance=1%
R18: library part ChipRes1, "Resistor, surface mount", Supplier Part Number 1=541-TNPW08058K56BEENCT-ND, Tolerance=1%
R21 R24 R25 R26 R27: library part ChipRes1, "Resistor, surface mount", Supplier Part Number 1=P4.99KDACT-ND, Tolerance=1%
U1: library part MAX333Acompact, "Quad SPDT analog switch", Part Number=MAX333AEWP+-ND
U2: library part CMP-0244-00130-1, "1.5A, Very-Low Drop Voltage Regulator, 3.3V, 3-Pin DPAK"
U3 U4: "Dual buffer", Supplier Part Number 1=296-27364-1-ND

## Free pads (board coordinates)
  round 180 hole 140: 4(3145,4325) 5(3945,4325) 6(4775,4325) 7(5790,4325) 8(-220,200) 8(-220,4325) 8(200,200) 8(200,4325) 8(6405,200) 9(3205,2015) 10(3995,2015) 11(4820,2015) 12(5790,2015)

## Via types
v1: diameter 50, hole 28, Top Layer to Bottom Layer, tented both sides, 43 vias
v2: diameter 100, hole 58, Top Layer to Bottom Layer, tented both sides, 4 vias

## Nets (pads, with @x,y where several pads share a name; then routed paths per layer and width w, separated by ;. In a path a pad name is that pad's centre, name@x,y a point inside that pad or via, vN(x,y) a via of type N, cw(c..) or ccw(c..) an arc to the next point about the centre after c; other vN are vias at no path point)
24VIN: +24VIN.1 FL2.1 P7.2 | length 1792.1
  Top Layer w30: FL2.1@6148.43,2823.43 6326.57,2823.43 +24VIN.1@6425,2725
  Bottom Layer w100: FL2.1@6148.43,2823.43 6148.43,3673.43 6325,3850 P7.2@6325,4225
+3.3V1: +3.3V1.1 C23.2 C25.2 C26.2 C27.2 C28.2 C32.2 L5.2 PO3.1 PO3.2 PO3.12 PO3.13 PO4.1 PO4.2 PO4.12 PO4.13 R5.1 | length 9208.1
  Top Layer w20: PO4.2@5315,3899.6 5412.28,3802.32 5749.06,3802.32 +3.3V1.1@5750,3801.38 5763.62,3815 5977.6,3815 R5.1@5987.6,3825
  Top Layer w100: PO3.13@4288,4065 PO3.1@4505,4065 ; PO3.2@4505,3899.6 PO3.1@4505,4065 ; PO4.2@5315,3899.6 PO4.1@5315,4065 PO4.13@5098,4065 PO3.1@4505,4065
  Top Layer w150: v2(4632,1475) L5.2@4632,1650
  Bottom Layer w30: C32.2@4325,1594.88 C28.2@4450,1594.88 C27.2@4573.03,1594.88 ; C27.2@4556.54,1578.39 C27.2@4573.03,1594.88 ; v2(4632,1475) 4575,1532 C27.2@4575,1594.88 ; C23.2@4862.77,1578.39 4846.27,1594.88 C23.2@4824.62,1594.88 C25.2@4700,1594.88 C27.2@4575,1594.88 ; C27.2@4573.03,1594.88 C27.2@4575,1594.88
  Bottom Layer w40: C26.2@4571.54,1375 4572.87,1375 4573.19,1375.31 4573.19,1416.19 v2(4632,1475)
  Bottom Layer w150: PO3.13@4288,4065 4339.6,4065 ; PO3.12@4505,2245.6 4712.13,2245.6 4800,2333.47 4800,4065 ; PO4.12@5315,2245.6 5482.13,2245.6 5570,2333.47 5570,3977.13 5482.13,4065 PO4.1@5315,4065 ; 4339.6,4065 PO3.2@4505,3899.6 PO3.1@4505,4065 ; 4339.6,4065 PO3.1@4505,4065 ; PO3.1@4505,4065 4800,4065 ; 4800,4065 PO4.13@5098,4065 5149.6,4065 ; 5149.6,4065 PO4.2@5315,3899.6 PO4.1@5315,4065 ; 5149.6,4065 PO4.1@5315,4065
+3.3V2: +3.3V2.1 C35.2 C37.2 C38.2 C39.2 C40.2 C44.2 L4.2 PO1.1 PO1.2 PO1.12 PO1.13 PO2.1 PO2.2 PO2.12 PO2.13 R4.1 R21.1 | length 11417.8
  Top Layer w10: L4.2@3608.5,1737.64 3682,1664.14 L4.2@3682,1650
  Top Layer w20: PO2.2@3715,3899.6 3799.6,3815 5120,3815 5285,3650 5701.38,3650 +3.3V2.1@5750,3601.38 5758.62,3610 5972.6,3610 R4.1@5987.6,3625
  Top Layer w100: PO1.13@2688,4065 PO1.1@2905,4065 ; PO1.2@2905,3899.6 PO1.1@2905,4065 ; PO2.2@3715,3899.6 PO2.1@3715,4065 PO2.13@3498,4065 PO1.1@2905,4065
  Top Layer w150: v2(3682,1485) L4.2@3682,1650
  Bottom Layer w30: C44.2@3375,1593.07 C39.2@3625,1593.07 ; C38.2@3621.54,1375 3621.54,1589.61 C39.2@3625,1593.07 ; C35.2@3889.68,1578.39 3875,1593.07 C39.2@3625,1593.07
  Bottom Layer w50: R21.1@2380.12,4375 2379.06,4373.94 PO1.13@2688,4065
  Bottom Layer w150: PO1.13@2688,4065 2739.6,4065 ; PO1.12@2905,2245.6 3087.13,2245.6 3175,2333.47 3175,4065 ; 3549.6,4065 3632.3,3982.3 ; PO2.12@3715,2245.6 3887.13,2245.6 3975,2333.47 3975,3935 3845,4065 PO2.1@3715,4065 ; 2739.6,4065 PO1.2@2905,3899.6 PO1.1@2905,4065 ; 2739.6,4065 PO1.1@2905,4065 ; PO1.1@2905,4065 3175,4065 ; 3175,4065 PO2.13@3498,4065 PO2.1@3715,4065 ; 3632.3,3982.3 PO2.1@3715,4065 ; 3632.3,3982.3 PO2.2@3715,3899.6 PO2.1@3715,4065
+5V: +5V.1 C47.2 C49.2 C50.2 C51.2 C52.2 C56.2 L3.2 P3.4 PO1.4 PO1.6 PO1.21 PO1.22 PO1.23 PO2.4 PO2.6 PO2.21 PO2.22 PO2.23 PO3.4 PO3.6 PO3.21 PO3.22 PO3.23 PO4.4 PO4.6 PO4.21 PO4.22 PO4.23 R3.1 R9.1 R13.1 R16.1 R19.1 R20.1 | length 9047.3
  Top Layer w20: L3.2@2732,1650 2732,1676.21 L3.2@2800.5,1744.71 ; PO4.6@5315,3238 5330.69,3238 5496.09,3403.4 +5V.1@5750,3403.4 5756.57,3409.97 5972.57,3409.97 R3.1@5987.6,3425
  Top Layer w150: v2(2732,1475) L3.2@2732,1650
  Bottom Layer w20: PO1.21@2688,2741.8 R20.1@2761.54,2741.8 R19.1@2761.54,2825 ; PO2.21@3498,2741.8 R16.1@3571.54,2741.8 ; PO3.21@4288,2741.8 R13.1@4366.54,2741.8 ; PO4.21@5098,2741.8 R9.1@5176.54,2741.8
  Bottom Layer w30: C56.2@2430,1594.88 C52.2@2555,1594.88 C51.2@2680,1594.88 ; C50.2@2671.54,1375 2671.54,1586.42 C51.2@2680,1594.88 ; C47.2@2946.5,1578.39 C47.2@2930,1594.88 C49.2@2805,1594.88 C51.2@2680,1594.88
  Bottom Layer w60: PO1.23@2688,2411 PO1.22@2688,2576.4 PO1.21@2688,2741.8 2605,2824.8 2605,3435 2655,3485 2790,3485 ; PO1.6@2905,3238 2790,3353 2790,3485 ; PO1.4@2905,3568.8 2821.2,3485 2790,3485 ; PO2.23@3498,2411 PO2.22@3498,2576.4 PO2.21@3498,2741.8 3405,2834.8 3405,3435 3455,3485 3595,3485 ; PO2.6@3715,3238 3595,3358 3595,3485 ; PO2.4@3715,3568.8 3631.2,3485 3595,3485 ; PO3.23@4288,2411 PO3.22@4288,2576.4 PO3.21@4288,2741.8 4206.8,2823 4206.8,3441.8 4255,3490 4395,3490 ; PO3.6@4505,3238 4395,3348 4395,3490 ; PO3.4@4505,3568.8 4426.2,3490 4395,3490 ; PO4.23@5098,2411 PO4.22@5098,2576.4 PO4.21@5098,2741.8 5015,2824.8 5015,3449.85 5050.15,3485 5195,3485 ; PO4.6@5315,3238 5195,3358 5195,3485 ; PO4.4@5315,3568.8 5231.2,3485 5195,3485
+5VSB1: PO1.9 R20.2 | length 76.5
  Bottom Layer w20: R20.2@2828.46,2741.8 PO1.9@2905,2741.8
+5VSB2: PO2.9 R16.2 | length 76.5
  Bottom Layer w20: R16.2@3638.46,2741.8 PO2.9@3715,2741.8
+5VSB3: PO3.9 R13.2 | length 71.5
  Bottom Layer w20: R13.2@4433.46,2741.8 PO3.9@4505,2741.8
+5VSB4: PO4.9 R9.2 | length 71.5
  Bottom Layer w20: R9.2@5243.46,2741.8 PO4.9@5315,2741.8
+12V: +12V.1 C11.2 C13.2 C14.2 C15.2 C16.2 C20.2 L6.2 P3.1 P4.1 PO1.10 PO1.11 PO2.10 PO2.11 PO3.10 PO3.11 PO4.10 PO4.11 R2.1 | length 5042.2
  Top Layer w20: PO4.10@5315,2576.4 5750,3011.4 +12V.1@5750,3200 5763.27,3213.27 5975.87,3213.27 R2.1@5987.6,3225
  Top Layer w64: PO1.11@2905,2411 2905,2495 ; PO1.10@2905,2576.4 2905,2495 ; PO2.11@3715,2411 3715,2495 ; PO2.10@3715,2576.4 3715,2495 ; PO3.11@4505,2411 4505,2495 ; PO3.10@4505,2576.4 4505,2495 ; PO4.11@5315,2411 5315,2495 ; PO4.10@5315,2576.4 5315,2495 ; 2905,2495 3715,2495 ; 3715,2495 4505,2495 ; 4505,2495 5315,2495
  Top Layer w150: v2(5582,1475) L6.2@5582,1650
  Bottom Layer w30: C20.2@5275,1594.88 C16.2@5400,1594.88 C15.2@5523.03,1594.88 ; C14.2@5521.54,1375 5521.54,1593.39 C15.2@5523.03,1594.88 ; C11.2@5791.5,1578.39 C11.2@5775,1594.88 C13.2@5650,1594.88 C15.2@5525,1594.88 C15.2@5523.03,1594.88
ENSELF: MD1.33 P6.1 R28.1 U1.1 U1.10 U1.11 | length 4979.9
  Top Layer w10: v1(1450,2995) 1388,3057 1388,4014.1 1605,4231.1 v1(1615,4231.1)
  Bottom Layer w10: v1(1615,4231.1) U1.1@1675,4231.1 1675,4315 1715,4355 2085,4355 2125,4315 U1.10@2125,4231.1 2125,3875 U1.11@2130,3870
  Bottom Layer w20: MD1.33@726.18,874.62 726.18,965.75 775,1014.57 R28.1@775,1016.54 986.54,1016.54 1325,1355 1325,2550 P6.1@1450,2675 v1(1450,2995)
